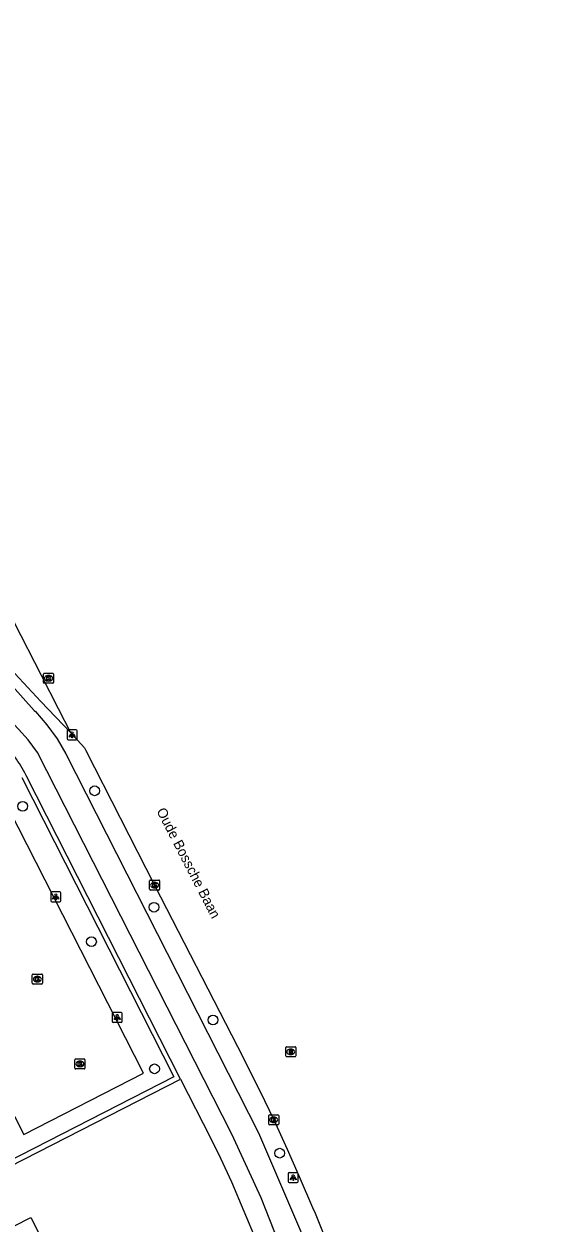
# Model space of a CAD drawing. Extents: x 158838 to 160074, y 386376 to 387776.
# Drawn here: x 159597.5 to 159650.7, y 386846.6 to 386967 of the extents above; entities that cross this region are included whole.
import ezdxf

# ---------------------------------------------------------------- set-up
doc = ezdxf.new("R2010")
doc.units = 0
for name, color, linetype in [('IMGEO_Boom', 7, 'Continuous'), ('IMGEO_Fietspad_gesloten', 7, 'Continuous'), ('IMGEO_Haag', 7, 'Continuous'), ('IMGEO_Kolk', 7, 'Continuous'), ('IMGEO_Lichtpunt', 7, 'Continuous'), ('IMGEO_Openbare_ruimte_label', 7, 'Continuous'), ('IMGEO_Pand_vergunning_verleend', 7, 'Continuous'), ('IMGEO_Parkeervlak_open', 7, 'Continuous'), ('IMGEO_Rijbaan_lokaal_gesloten', 7, 'Continuous'), ('IMGEO_Rioolput', 7, 'Continuous'), ('IMGEO_Voetpad_open', 7, 'Continuous')]:
    doc.layers.add(name, color=color, linetype=linetype)

msp = doc.modelspace()

# ---------------------------------------------------------------- linework, layer by layer
at = {"layer": 'IMGEO_Boom'}
for centre in [(159604.59, 386890.03), (159597.36, 386888.48), (159610.55, 386878.34), (159604.28, 386874.88), (159616.48, 386867.02), (159610.61, 386862.11), (159623.18, 386853.64)]:
    msp.add_circle(centre, 0.489, dxfattribs=at)
at = {"layer": 'IMGEO_Fietspad_gesloten'}
for points in [[(159627.53, 386833.35), (159621.31, 386849.17), (159618.37, 386855.55), (159598.86, 386893.88), (159597.91, 386895.15), (159596.95, 386896.22), (159592.15, 386901.32), (159591.97, 386901.51), (159591.39, 386902.22), (159590.88, 386902.97), (159590.43, 386903.77), (159585.83, 386912.64), (159585.68, 386912.94), (159585.34, 386913.75), (159585.08, 386914.6), (159584.89, 386915.46), (159583.35, 386923.32), (159583.2, 386923.92), (159583, 386924.5), (159582.74, 386925.06), (159582.67, 386925.21), (159563.21, 386963), (159561.12, 386967.04)], [(159593.28, 386903.95), (159598.54, 386898.11), (159598.65, 386897.99), (159599.8, 386896.66), (159600.82, 386895.24), (159601.71, 386893.73), (159621.05, 386855.67), (159626.87, 386842.09), (159629.74, 386834.58), (159634.33, 386821.17), (159636.85, 386811.73), (159638.01, 386806.95), (159640.72, 386798.09), (159643.94, 386790.09), (159646.12, 386785.73)]]:
    msp.add_lwpolyline(points, dxfattribs=at)
at = {"layer": 'IMGEO_Haag'}
for points in [[(159597.28, 386891.35), (159612.56, 386861.3), (159561.98, 386835.43), (159552.94, 386853.16)], [(159561.76, 386834.76), (159613.23, 386861.08)]]:
    msp.add_lwpolyline(points, dxfattribs=at)
at = {"layer": 'IMGEO_Kolk'}
for p, q in [((159599.47, 386900.9), (159599.47, 386901.75)), ((159599.54, 386901.83), (159600.39, 386901.83)), ((159599.95, 386901.61), (159599.98, 386901.61)), ((159599.98, 386901.05), (159599.95, 386901.05)), ((159600.47, 386901.75), (159600.47, 386900.9)), ((159600.39, 386900.83), (159599.54, 386900.83)), ((159610.12, 386880.14), (159610.12, 386880.99)), ((159610.2, 386881.07), (159611.05, 386881.07)), ((159610.61, 386880.84), (159610.63, 386880.84)), ((159611.12, 386880.99), (159611.12, 386880.14)), ((159611.05, 386880.06), (159610.2, 386880.06)), ((159610.63, 386880.29), (159610.61, 386880.29)), ((159598.34, 386870.7), (159598.34, 386871.55)), ((159598.42, 386871.62), (159599.27, 386871.62)), ((159598.83, 386871.4), (159598.86, 386871.4)), ((159598.85, 386870.84), (159598.83, 386870.84)), ((159599.35, 386871.55), (159599.35, 386870.7)), ((159599.27, 386870.62), (159598.42, 386870.62)), ((159602.62, 386862.17), (159602.62, 386863.02)), ((159602.7, 386863.1), (159603.55, 386863.1)), ((159603.11, 386862.88), (159603.13, 386862.88)), ((159603.62, 386863.02), (159603.62, 386862.17)), ((159603.55, 386862.1), (159602.7, 386862.1)), ((159603.13, 386862.32), (159603.11, 386862.32)), ((159622.08, 386856.56), (159622.08, 386857.41)), ((159622.15, 386857.49), (159623.01, 386857.49)), ((159623.01, 386856.49), (159622.15, 386856.49)), ((159622.59, 386856.71), (159622.56, 386856.71)), ((159622.57, 386857.27), (159622.59, 386857.27)), ((159623.08, 386857.41), (159623.08, 386856.56))]:
    msp.add_line(p, q, dxfattribs=at)
for points in [[(159599.47, 386900.9), (159599.47, 386901.75)], [(159599.54, 386901.83), (159600.39, 386901.83)], [(159599.79, 386901.53), (159599.91, 386901.53), (159599.91, 386901.38), (159600.04, 386901.53), (159600.2, 386901.53), (159600.06, 386901.38), (159600.21, 386901.13), (159600.06, 386901.13), (159599.97, 386901.29), (159599.91, 386901.22), (159599.91, 386901.13), (159599.79, 386901.13), (159599.79, 386901.53)], [(159600.47, 386901.75), (159600.47, 386900.9)], [(159600.39, 386900.83), (159599.54, 386900.83)], [(159610.12, 386880.14), (159610.12, 386880.99)], [(159610.2, 386881.07), (159611.05, 386881.07)], [(159610.44, 386880.76), (159610.57, 386880.76), (159610.57, 386880.61), (159610.69, 386880.76), (159610.86, 386880.76), (159610.71, 386880.61), (159610.87, 386880.36), (159610.71, 386880.36), (159610.63, 386880.53), (159610.57, 386880.46), (159610.57, 386880.36), (159610.44, 386880.36), (159610.44, 386880.76)], [(159611.12, 386880.99), (159611.12, 386880.14)], [(159611.05, 386880.06), (159610.2, 386880.06)], [(159598.34, 386870.7), (159598.34, 386871.55)], [(159598.42, 386871.62), (159599.27, 386871.62)], [(159598.66, 386871.32), (159598.79, 386871.32), (159598.79, 386871.17), (159598.92, 386871.32), (159599.08, 386871.32), (159598.94, 386871.17), (159599.09, 386870.92), (159598.94, 386870.92), (159598.85, 386871.09), (159598.79, 386871.02), (159598.79, 386870.92), (159598.66, 386870.92), (159598.66, 386871.32)], [(159599.35, 386871.55), (159599.35, 386870.7)], [(159599.27, 386870.62), (159598.42, 386870.62)], [(159602.62, 386862.17), (159602.62, 386863.02)], [(159602.7, 386863.1), (159603.55, 386863.1)], [(159602.94, 386862.8), (159603.07, 386862.8), (159603.07, 386862.65), (159603.19, 386862.8), (159603.36, 386862.8), (159603.21, 386862.65), (159603.37, 386862.4), (159603.21, 386862.4), (159603.13, 386862.56), (159603.07, 386862.5), (159603.07, 386862.4), (159602.94, 386862.4), (159602.94, 386862.8)], [(159603.62, 386863.02), (159603.62, 386862.17)], [(159603.55, 386862.1), (159602.7, 386862.1)], [(159622.08, 386856.56), (159622.08, 386857.41)], [(159622.15, 386857.49), (159623.01, 386857.49)], [(159623.01, 386856.49), (159622.15, 386856.49)], [(159622.4, 386857.19), (159622.52, 386857.19), (159622.52, 386857.04), (159622.65, 386857.19), (159622.82, 386857.19), (159622.67, 386857.04), (159622.82, 386856.79), (159622.67, 386856.79), (159622.59, 386856.95), (159622.52, 386856.89), (159622.52, 386856.79), (159622.4, 386856.79), (159622.4, 386857.19)], [(159623.08, 386857.41), (159623.08, 386856.56)]]:
    msp.add_lwpolyline(points, dxfattribs=at)
for centre, start, end in [((159599.54, 386901.75), 91.552, 178.448), ((159599.54, 386901.75), 91.552, 178.448), ((159600.39, 386901.75), 1.552, 88.448), ((159600.39, 386901.75), 1.552, 88.448), ((159599.54, 386900.9), 181.552, 268.448), ((159599.54, 386900.9), 181.552, 268.448), ((159600.39, 386900.9), 271.552, 358.448), ((159600.39, 386900.9), 271.552, 358.448), ((159610.2, 386880.99), 91.552, 178.448), ((159610.2, 386880.99), 91.552, 178.448), ((159611.05, 386880.99), 1.552, 88.448), ((159611.05, 386880.99), 1.552, 88.448), ((159610.2, 386880.14), 181.552, 268.448), ((159610.2, 386880.14), 181.552, 268.448), ((159611.05, 386880.14), 271.552, 358.448), ((159611.05, 386880.14), 271.552, 358.448), ((159598.42, 386871.55), 91.552, 178.448), ((159598.42, 386871.55), 91.552, 178.448), ((159599.27, 386871.55), 1.552, 88.448), ((159599.27, 386871.55), 1.552, 88.448), ((159598.42, 386870.7), 181.552, 268.448), ((159598.42, 386870.7), 181.552, 268.448), ((159599.27, 386870.7), 271.552, 358.448), ((159599.27, 386870.7), 271.552, 358.448), ((159602.7, 386863.02), 91.552, 178.448), ((159602.7, 386863.02), 91.552, 178.448), ((159603.55, 386863.02), 1.552, 88.448), ((159603.55, 386863.02), 1.552, 88.448), ((159602.7, 386862.17), 181.552, 268.448), ((159602.7, 386862.17), 181.552, 268.448), ((159603.55, 386862.17), 271.552, 358.448), ((159603.55, 386862.17), 271.552, 358.448), ((159622.16, 386857.41), 91.552, 178.448), ((159622.16, 386857.41), 91.552, 178.448), ((159622.16, 386856.56), 181.552, 268.448), ((159622.16, 386856.56), 181.552, 268.448), ((159623, 386857.41), 1.552, 88.448), ((159623, 386857.41), 1.552, 88.448), ((159623, 386856.56), 271.552, 358.448), ((159623, 386856.56), 271.552, 358.448)]:
    msp.add_arc(centre, 0.0765, start, end, dxfattribs=at)
for centre, major_axis, ratio, start_param, end_param in [((159599.95, 386901.33), (-0.387, 0.002), 0.722429, 4.712389, 7.853982), ((159599.98, 386901.33), (-0.39, 0.002), 0.717154, 1.570796, 4.712389), ((159610.61, 386880.56), (-0.387, 0.002), 0.722429, 4.712389, 7.853982), ((159610.63, 386880.56), (-0.39, 0.002), 0.717154, 1.570796, 4.712389), ((159598.83, 386871.12), (-0.387, 0.002), 0.722429, 4.712389, 7.853982), ((159598.86, 386871.12), (-0.39, 0.002), 0.717154, 1.570796, 4.712389), ((159603.11, 386862.6), (-0.387, 0.002), 0.722429, 4.712389, 7.853982), ((159603.13, 386862.6), (-0.39, 0.002), 0.717154, 1.570796, 4.712389), ((159622.57, 386856.99), (-0.387, 0.002), 0.722429, 4.712389, 7.853982), ((159622.59, 386856.99), (-0.39, 0.002), 0.717154, 1.570796, 4.712389)]:
    msp.add_ellipse(centre, major_axis=major_axis, ratio=ratio, start_param=start_param, end_param=end_param, dxfattribs=at)
at = {"layer": 'IMGEO_Lichtpunt'}
for p, q in [((159602.74, 386896.15), (159601.93, 386896.15)), ((159602.74, 386896.15), (159601.93, 386896.15)), ((159601.84, 386896.06), (159601.84, 386895.25)), ((159601.84, 386896.06), (159601.84, 386895.25)), ((159601.93, 386895.16), (159602.74, 386895.16)), ((159601.93, 386895.16), (159602.74, 386895.16)), ((159602.84, 386895.25), (159602.84, 386896.06)), ((159602.84, 386895.25), (159602.84, 386896.06)), ((159600.2, 386879.79), (159600.2, 386878.98)), ((159600.2, 386879.79), (159600.2, 386878.98)), ((159601.1, 386879.88), (159600.29, 386879.88)), ((159601.1, 386879.88), (159600.29, 386879.88)), ((159601.19, 386878.98), (159601.19, 386879.79)), ((159601.19, 386878.98), (159601.19, 386879.79)), ((159600.29, 386878.89), (159601.1, 386878.89)), ((159600.29, 386878.89), (159601.1, 386878.89)), ((159606.37, 386867.68), (159606.37, 386866.87)), ((159606.37, 386867.68), (159606.37, 386866.87)), ((159607.27, 386867.78), (159606.46, 386867.78)), ((159607.27, 386867.78), (159606.46, 386867.78)), ((159607.37, 386866.87), (159607.37, 386867.68)), ((159607.37, 386866.87), (159607.37, 386867.68)), ((159606.46, 386866.78), (159607.27, 386866.78)), ((159606.46, 386866.78), (159607.27, 386866.78)), ((159624.04, 386851.59), (159624.04, 386850.78)), ((159624.04, 386851.59), (159624.04, 386850.78)), ((159624.95, 386851.68), (159624.14, 386851.68)), ((159624.95, 386851.68), (159624.14, 386851.68)), ((159625.04, 386850.78), (159625.04, 386851.59)), ((159625.04, 386850.78), (159625.04, 386851.59)), ((159624.14, 386850.68), (159624.95, 386850.68)), ((159624.14, 386850.68), (159624.95, 386850.68))]:
    msp.add_line(p, q, dxfattribs=at)
for points in [[(159602.21, 386895.72), (159602.25, 386895.7), (159602.07, 386895.43), (159602.03, 386895.46), (159602.21, 386895.72)], [(159602.32, 386895.68), (159602.36, 386895.68), (159602.36, 386895.35), (159602.32, 386895.35), (159602.32, 386895.68)], [(159602.43, 386895.7), (159602.46, 386895.72), (159602.65, 386895.46), (159602.61, 386895.43), (159602.43, 386895.7)], [(159600.57, 386879.45), (159600.61, 386879.43), (159600.42, 386879.16), (159600.38, 386879.19), (159600.57, 386879.45)], [(159600.67, 386879.41), (159600.72, 386879.41), (159600.72, 386879.08), (159600.67, 386879.08), (159600.67, 386879.41)], [(159600.78, 386879.43), (159600.82, 386879.45), (159601.01, 386879.19), (159600.97, 386879.16), (159600.78, 386879.43)], [(159606.74, 386867.34), (159606.78, 386867.32), (159606.59, 386867.05), (159606.56, 386867.08), (159606.74, 386867.34)], [(159606.84, 386867.3), (159606.89, 386867.3), (159606.89, 386866.97), (159606.84, 386866.97), (159606.84, 386867.3)], [(159606.95, 386867.32), (159606.99, 386867.34), (159607.18, 386867.08), (159607.14, 386867.05), (159606.95, 386867.32)], [(159624.42, 386851.25), (159624.46, 386851.22), (159624.27, 386850.96), (159624.23, 386850.99), (159624.42, 386851.25)], [(159624.52, 386851.2), (159624.57, 386851.2), (159624.57, 386850.88), (159624.52, 386850.88), (159624.52, 386851.2)], [(159624.63, 386851.22), (159624.67, 386851.25), (159624.85, 386850.99), (159624.82, 386850.96), (159624.63, 386851.22)]]:
    msp.add_lwpolyline(points, dxfattribs=at)
for centre in [(159602.34, 386895.86), (159600.7, 386879.59), (159606.87, 386867.48), (159624.54, 386851.38)]:
    msp.add_circle(centre, 0.0994, dxfattribs=at)
for centre, start, end in [((159601.93, 386896.06), 90, 180), ((159601.93, 386896.06), 90, 180), ((159602.74, 386896.06), 0, 90), ((159602.74, 386896.06), 0, 90), ((159601.93, 386895.25), 180, 270), ((159601.93, 386895.25), 180, 270), ((159602.74, 386895.25), 270, 0), ((159602.74, 386895.25), 270, 360), ((159600.29, 386879.79), 90, 180), ((159600.29, 386879.79), 90, 180), ((159601.1, 386879.79), 0, 90), ((159601.1, 386879.79), 0, 90), ((159600.29, 386878.98), 180, 270), ((159600.29, 386878.98), 180, 270), ((159601.1, 386878.98), 270, 0), ((159601.1, 386878.98), 270, 360), ((159606.46, 386867.68), 90, 180), ((159606.46, 386867.68), 90, 180), ((159607.27, 386867.68), 0, 90), ((159607.27, 386867.68), 0, 90), ((159606.46, 386866.87), 180, 270), ((159606.46, 386866.87), 180, 270), ((159607.27, 386866.87), 270, 0), ((159607.27, 386866.87), 270, 360), ((159624.14, 386851.59), 90, 180), ((159624.14, 386851.59), 90, 180), ((159624.95, 386851.59), 0, 90), ((159624.95, 386851.59), 0, 90), ((159624.14, 386850.78), 180, 270), ((159624.14, 386850.78), 180, 270), ((159624.95, 386850.78), 270, 0), ((159624.95, 386850.78), 270, 360)]:
    msp.add_arc(centre, 0.0946, start, end, dxfattribs=at)
at = {"layer": 'IMGEO_Pand_vergunning_verleend'}
msp.add_lwpolyline([(159572.53, 386834.08), (159598.18, 386847.17), (159602.21, 386839.27), (159603.96, 386840.16), (159608.27, 386831.7), (159604.3, 386829.68), (159608.25, 386821.92), (159612.25, 386823.96), (159616.5, 386815.63), (159591.76, 386803), (159587.56, 386811.23), (159583.47, 386819.24), (159582.15, 386818.57), (159578.01, 386826.68), (159576.65, 386825.99), (159572.53, 386834.08)], dxfattribs=at)
at = {"layer": 'IMGEO_Parkeervlak_open'}
msp.add_lwpolyline([(159563.74, 386878.18), (159581.32, 386887.17), (159597.5, 386855.53), (159609.52, 386861.67), (159591.48, 386896.95), (159592.3, 386897.37)], dxfattribs=at)
at = {"layer": 'IMGEO_Rijbaan_lokaal_gesloten'}
for points in [[(159587.27, 386924.87), (159587.83, 386923.8), (159590.93, 386917.86), (159593.14, 386913.61), (159596.53, 386906.94), (159599.22, 386901.63), (159600.93, 386898.31), (159602.18, 386895.88)], [(159602.18, 386895.88), (159599.21, 386899), (159595.72, 386902.75), (159595.4, 386903.16), (159594.63, 386904.67)], [(159602.18, 386895.88), (159603.57, 386894.36), (159603.72, 386894.07), (159610.62, 386880.56), (159618.94, 386864.35), (159621.18, 386859.9), (159622.58, 386856.99), (159623.94, 386854.04), (159625.15, 386851.3), (159626.49, 386848.18), (159626.73, 386847.61), (159629.04, 386841.81), (159636.18, 386822.64), (159639.07, 386814.94), (159641.24, 386809.36), (159643.56, 386803.65), (159644.52, 386801.54), (159648.73, 386792.66), (159650.73, 386788.49)]]:
    msp.add_lwpolyline(points, dxfattribs=at)
at = {"layer": 'IMGEO_Rioolput'}
for p, q in [((159623.79, 386863.4), (159623.79, 386864.25)), ((159623.87, 386864.32), (159624.72, 386864.32)), ((159624.28, 386864.1), (159624.3, 386864.1)), ((159624.79, 386864.25), (159624.79, 386863.4)), ((159624.72, 386863.32), (159623.87, 386863.32)), ((159624.3, 386863.54), (159624.28, 386863.54))]:
    msp.add_line(p, q, dxfattribs=at)
for points in [[(159623.79, 386863.4), (159623.79, 386864.25)], [(159623.87, 386864.32), (159624.72, 386864.32)], [(159624.38, 386864.02), (159624.13, 386864.02), (159624.13, 386863.62)], [(159624.13, 386863.62), (159624.25, 386863.62), (159624.25, 386863.78), (159624.26, 386863.78)], [(159624.31, 386863.94), (159624.25, 386863.94), (159624.25, 386863.86)], [(159624.25, 386863.86), (159624.3, 386863.86)], [(159624.31, 386863.75), (159624.38, 386863.62), (159624.52, 386863.62), (159624.46, 386863.75)], [(159624.79, 386864.25), (159624.79, 386863.4)], [(159624.72, 386863.32), (159623.87, 386863.32)]]:
    msp.add_lwpolyline(points, dxfattribs=at)
for centre, radius, start, end in [((159623.87, 386864.25), 0.0765, 91.552, 178.448), ((159623.87, 386864.25), 0.0765, 91.552, 178.448), ((159624.26, 386863.73), 0.0533, 26.0293, 88.6989), ((159624.29, 386864.05), 0.19, 274.7715, 282.9687), ((159624.31, 386863.84), 0.0964, 77.0061, 93.1865), ((159624.33, 386863.9), 0.0378, 276.6634, 79.6772), ((159624.38, 386863.91), 0.109, 350.3612, 89.416), ((159624.38, 386863.91), 0.112, 277.5842, 350.9817), ((159624.36, 386863.69), 0.108, 29.5134, 73.7905), ((159624.72, 386864.25), 0.0765, 1.552, 88.448), ((159624.72, 386864.25), 0.0765, 1.552, 88.448), ((159623.87, 386863.4), 0.0765, 181.552, 268.448), ((159623.87, 386863.4), 0.0765, 181.552, 268.448), ((159624.72, 386863.4), 0.0765, 271.552, 358.448), ((159624.72, 386863.4), 0.0765, 271.552, 358.448)]:
    msp.add_arc(centre, radius, start, end, dxfattribs=at)
for centre, major_axis, ratio, start_param, end_param in [((159624.28, 386863.82), (-0.387, 0.002), 0.722429, 4.712389, 7.853982), ((159624.3, 386863.82), (-0.39, 0.002), 0.717154, 1.570796, 4.712389)]:
    msp.add_ellipse(centre, major_axis=major_axis, ratio=ratio, start_param=start_param, end_param=end_param, dxfattribs=at)
at = {"layer": 'IMGEO_Voetpad_open'}
for points in [[(159613.23, 386861.08), (159597.73, 386891.58)], [(159613.23, 386861.08), (159616.27, 386855.11), (159617.25, 386853.15), (159618.33, 386850.76), (159620.83, 386844.87), (159620.86, 386844.81), (159625.56, 386832.68), (159630.35, 386818.53), (159630.77, 386816.95)]]:
    msp.add_lwpolyline(points, dxfattribs=at)
msp.add_arc((159586.05, 386885.7), 13.07, 26.7196, 45.7923, dxfattribs=at)

# ---------------------------------------------------------------- texts
at = {"layer": 'IMGEO_Openbare_ruimte_label'}
msp.add_text('Oude Bossche Baan', height=1, rotation=297.2569, dxfattribs=at).set_placement((159610.78, 386888.01))

doc.saveas('drawing.dxf')
